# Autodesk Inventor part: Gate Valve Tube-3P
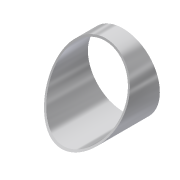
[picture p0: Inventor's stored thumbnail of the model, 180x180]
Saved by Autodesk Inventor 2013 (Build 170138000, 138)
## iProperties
Created: 2012-05
Part Number: Gate Valve Tube-3P
Material: Stainless Steel, 316
Document SubType Name: Modeling
Designer: ssc
Mass: 946.545 g
Surface Area: 801.814 cm^2
Volume: 119.062 cm^3
Density: 7.95 g/cm^3
Author: ssc
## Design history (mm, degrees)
sketch "Sketch1"
  geometry: C1 r 70.65 at (0, 0); C2 r 67.246 at (0, 0)
  constraints: 2 centre point, 1 coincident, 1 other
  dimensions: "d0" = 141.3002 diameter of C1; "d1" = 3.4036 radial gap between concentric circles of C2 C1
extrude "Extrusion1" new body sketch "Sketch1" distance "d2" = 152.4; taper "d3" = 0 deg
sketch "Sketch2"
  geometry: L1 (-70.65, 152.4)-(70.65, 152.4) reference; L2 (-70.65, 0)-(70.65, 0) reference; L3 (0, -193.802)-(0, 1162.812) reference; C1 r 476.25 at (241.3, 477.52)
  constraints: 1 centre point
  dimensions: "d4" = 241.3 distance from line of L3 C1.centre; "d5" = 952.5 diameter of C1; "d6" = 477.52 distance from line of C1.centre L2
extrude "Extrusion2" cut sketch "Sketch2" stored distance "d7" = 152.4; taper "d8" = 0 deg
body "Solid1"
node "Projected Loop1"
